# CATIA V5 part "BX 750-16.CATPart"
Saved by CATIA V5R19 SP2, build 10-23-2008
Part number: BX 750-16
Bounding box of the stored display mesh (mm): x -47.487 to 47.487, y -47.487 to 47.487, z 0 to 116
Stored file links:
  C:\Users\Bora\Desktop\3D Katı model\BX serisi\BX 750\BX 750-16.CATPart
  C:\Program Files\Dassault Systemes\B19\intel_a\reffiles\standard\MetricThickPitch.txt
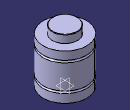
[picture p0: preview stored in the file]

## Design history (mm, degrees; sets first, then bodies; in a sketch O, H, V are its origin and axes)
Body1 (main body)
  Sketch1 on yz-plane, origin (0, 0, 0), H (0, 1, 0), V (0, 0, 1)
    point P2 (47.5, 18.5)
    line L1 (47.5, 18.5) -> (47.5, 0)
    point P3 (47.5, 23.5)
    point P4 (47.5, 76.5)
    line L2 (47.5, 76.5) -> (47.5, 23.5)
    point P6 (27.5, 115)
    arc A1 centre (26.5, 115) radius 1 from (27.5, 115) to (26.5, 116) ccw
    point P8 (27.5, 115)
    line L3 (27.5, 115) -> (27.5, 99)
    point P9 (47.5, 81.5)
    line L4 (47.5, 99) -> (47.5, 81.5)
    point P11 (47.5, 18.5)
    point P12 (47.5, 23.5)
    arc A2 centre (47.5, 21) radius 2.5 from (47.5, 23.5) to (47.5, 18.5) ccw
    point P13 (47.5, 76.5)
    point P14 (47.5, 81.5)
    arc A3 centre (47.5, 79) radius 2.5 from (47.5, 81.5) to (47.5, 76.5) ccw
    line L5 (26.5, 116) -> (0, 116)
    line L6 (27.5, 99) -> (47.5, 99)
    line L7 (47.5, 0) -> (0, 0)
    tangency: L5 A1
    horizontal: L6 H, L7 H
    coincidence: P2 P11, P3 P12, P4 P13, P6 P8, P9 P14
  Shaft1: profile Sketch1, axis Sketch1.V, angle 360
  Sketch2 on face of Shaft1 from Sketch1.L7, origin (0, 0, 0), H (1, 0, 0), V (0, -1, 0)
    point P1 (25, 0)
    distance P1 V = 25
  Hole1: placed by Sketch2, at (25, 0, 0) direction (0, 0, 1), diameter 6.647, depth 10, threaded "M8", thread diameter 8, thread depth 10, pitch 1.25
  CircPattern1: of Hole1, instances 4, angular step 90, axis from xy-plane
